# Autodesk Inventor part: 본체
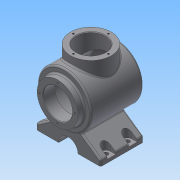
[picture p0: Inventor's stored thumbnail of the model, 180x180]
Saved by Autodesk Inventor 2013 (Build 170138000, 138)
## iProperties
Created: 2017-04
Part Number: 본체
Material: Generic
Document SubType Name: Modeling
Designer: Administrator
Density: 1 g/cm^3
Author: Administrator
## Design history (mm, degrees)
sketch "스케치1"
  geometry: L1 (-60, 0)-(60, 0); L2 (-60, 27)-(-60, 38); L3 (-60, 38)-(-48, 38); L4 (-48, 38)-(-48, 50); L5 (-48, 50)-(48.336, 50); L6 (41.916, 40)-(-38, 40); L7 (-38, 40)-(-38, 27); L8 (-38, 27)-(-60, 27); A1 r 113 centre (-53, 0) between (60, 0) and (48.336, 50); A2 r 103 centre (-53, 0) between (50, 0) and (41.916, 40); 2 further points
  constraints: 16 end point, 4 point on circle, 3 parallel, 2 centre point, 2 perpendicular, 2 point on line, 1 coincident, 1 horizontal, 1 midpoint, 1 vertical alignment, 1 other
  dimensions: "d0" = 113 radius of A1; "d2" = 120 distance from line of L1.end L2; "d3" = 76 diameter of L3 L1; "d4" = 100 diameter of L5 L1; "d5" = 12 distance between parallel lines of L4 L2; "d6" = 54 diameter of L8 L1; "d7" = 80 diameter of L6 L1; "d8" = 10 radial gap between concentric circles of A1 A2
revolve "회전1" sketch "스케치1" stored, may be unused: angle "d9" = 90 deg
node "작업 평면1"
sketch "스케치5"
  geometry: L1 (-82, 70)-(-82, -70) reference; L2 (-82, -60)-(-72, -60); L3 (-72, -60)-(-38.229, -11.77); L4 (-38.229, 11.77)-(-72, 60); L5 (-72, 60)-(-82, 60); A1 r 40 centre (0, 0) between (-38.229, -11.77) and (-38.229, 11.77) reference; 1 further point
  constraints: 8 end point, 2 perpendicular, 2 point on circle, 2 point on line, 1 vertical alignment
  dimensions: "d14" = 120 distance between parallel lines of L5 L2; "d16" = 60 distance from line of point (0, 0) L2; "d17" = 55 deg angle of L2 L3; "d18" = 55 deg angle of L5 L4; "d19" = 10 distance of L2.start L2.end
extrude "돌출1" join sketch "스케치5" stored distance "d20" = 80; taper "d21" = 0 deg
sketch "스케치6"
  geometry: L1 (-60, -82)-(60, -82) reference; C1 r 18 at (0, -82); A1 r 50 centre (0, 0) between (-21.584, -45.101) and (21.584, -45.101) reference; 1 further point
  constraints: 1 centre point, 1 coincident, 1 midpoint, 1 vertical alignment
  dimensions: "d22" = 36 diameter of C1
extrude "돌출2" cut sketch "스케치6" stored distance "d24" = 80; taper "d25" = 0 deg
node "작업 평면3"
sketch "스케치7"
  geometry: L1 (-40, 21.584)-(-40, 60) reference; L2 (40, 60)-(40, 21.584) reference; L3 (40, 60)-(-40, 60) reference; L4 (-12, 60)-(-12, 50); L5 (-28, 50)-(-28, 60); C1 r 4 at (-20, 50); A1 r 8 centre (-20, 50) between (-28, 50) and (-12, 50); 1 further point
  constraints: 4 end point, 2 centre point, 2 horizontal alignment, 2 point on circle, 2 point on line, 2 tangent, 1 coincident, 1 parallel, 1 perpendicular
  dimensions: "d27" = 20 distance from line of L1 C1.centre; "d28" = 8 radius of A1; "d29" = 8 diameter of C1; "d30" = 10 distance from line of L3 A1.centre
extrude "돌출3" cut sketch "스케치7" stored distance "d31" = 80; taper "d32" = 0 deg
sketch "스케치9"
  geometry: L1 (52, 32)-(52, 42) reference; L2 (68, 42)-(68, 32) reference; L3 (52, 42)-(68, 42); A1 r 8 centre (60, 32) between (52, 32) and (68, 32) reference; 1 further point
  constraints: 2 end point, 1 perpendicular
extrude "돌출4" join sketch "스케치9" distance "d33" = 6; taper "d34" = 0 deg
sketch "스케치11"
  geometry: C1 r 4 at (60, -32); A1 r 8 centre (60, -32) between (68, -32) and (52, -32) reference; 1 further point
  constraints: 1 centre point, 1 coincident
  dimensions: "d35" = 8 diameter of C1
extrude "돌출5" cut sketch "스케치11" stored distance "d37" = 6; taper "d38" = 0 deg
node "작업 평면4"
sketch "스케치13"
  geometry: L1 (48, 50)-(48, -50) reference; C1 r 38 at (-2, 0); 1 further point
  constraints: 1 centre point, 1 horizontal alignment
  dimensions: "d40" = 50 distance from line of L1 C1.centre; "d41" = 76 diameter of C1
extrude "돌출6" join sketch "스케치13" stored distance "d42" = 6; taper "d43" = 0 deg
fillet "모깎기1" dims "d44" = 3
fillet "모깎기2" dims "d45" = 3
fillet "모깎기3" dims "d46" = 3
fillet "모깎기4" dims "d47" = 3
fillet "모깎기5" dims "d48" = 3
sketch "스케치15"
  geometry: C1 r 38 at (0, 0) reference; C2 r 27 at (0, 0); 1 further point
  constraints: 1 centre point
  dimensions: "d49" = 54 diameter of C2
extrude "돌출7" cut sketch "스케치15" stored distance "d51" = 6; taper "d52" = 0 deg
chamfer "모따기1" distance "d53" = 1; stored, may be unused: second distance "d54" = 2, angle "d55" = 45 deg
sketch "스케치16"
  geometry: C1 r 38 at (0, 0) reference; 1 further point
  constraints: 1 vertical alignment
  dimensions: "d56" = 32.5 distance of C1.centre point (0, 32.5)
hole "구멍1" sketch "스케치16" at (0, 32.5) diameter "d57" = 3.242; stored, may be unused: countersink angle "d61" = 90 deg, drill point angle "d63" = 118 deg; dims "d58" = 8, "d59" = 4, "d60" = 2, "d62" = 10
sketch "스케치17"
  geometry: C1 r 38 at (0, 0) reference; 2 further points
  constraints: 1 vertical alignment
  dimensions: "d67" = 32.5 distance of C1.centre point (0, 32.5)
hole "구멍2" sketch "스케치17" at (0, 32.5) diameter "d68" = 3.242; stored, may be unused: countersink angle "d72" = 90 deg, drill point angle "d74" = 118 deg; dims "d69" = 8, "d70" = 4, "d71" = 2, "d73" = 10
node "작업 평면5"
sketch "스케치18"
  geometry: 2 further points
  constraints: 1 coincident, 1 other
feature "엠보싱1" sketch "스케치18" dims "d0" = 113, "d2" = 120, "d3" = 76, "d4" = 100, "d5" = 12, "d6" = 54, "d7" = 80, "d8" = 10, "d14" = 120, "d16" = 60, "d17" = 55 deg, "d18" = 55 deg, "d19" = 10, "d79" = 0.5, "d80" = 0
node "솔리드1"
mirror "대칭1"
mirror "대칭2"
mirror "대칭3"
pattern_circular "원형 패턴1" dims angle "d65" = 360 deg
pattern_circular "원형 패턴2" dims angle "d76" = 360 deg
other parameters: "d10" = -82, "d26" = -49.5, "d39" = 65, "d78" = 117.25
